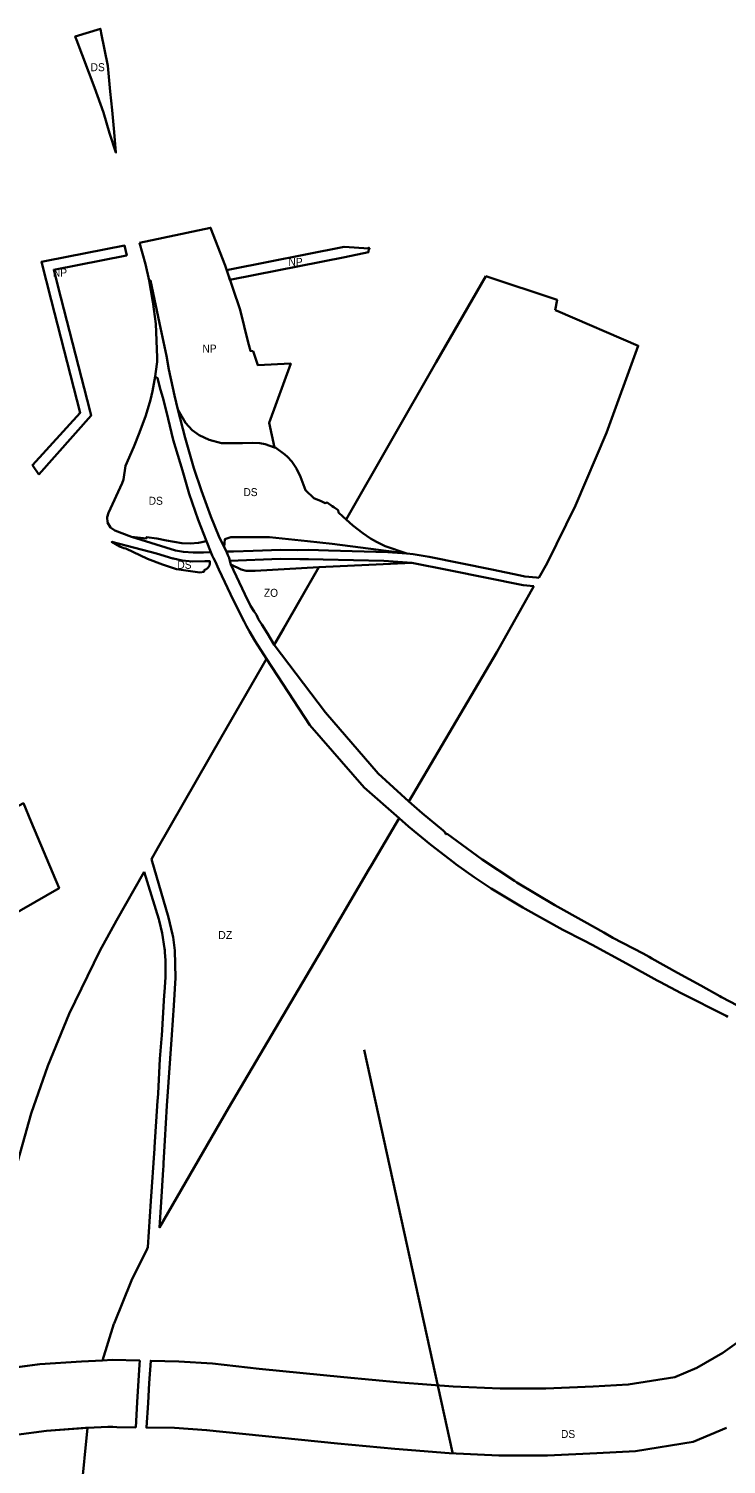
# Model space of a CAD drawing. Extents: x -650276 to -642489, y -1074311 to -1066658.
# Drawn here: x -647975 to -646929, y -1069108 to -1066956 of the extents above; entities that cross this region are included whole.
import ezdxf

# ---------------------------------------------------------------- set-up
doc = ezdxf.new("R2010")
doc.units = 0
doc.header["$LTSCALE"] = 4.8
doc.header["$PDMODE"] = 32
doc.header["$PDSIZE"] = 2.4
for name, color, linetype, lineweight in [('24', 7, 'Continuous', 35), ('25', 7, 'Continuous', 35), ('42', 7, 'Continuous', 35), ('48', 7, 'Continuous', 35), ('54', 7, 'Continuous', 35)]:
    doc.layers.add(name, color=color, linetype=linetype, lineweight=lineweight)
doc.layers.add('62', color=7, linetype='Continuous')
doc.layers.add('63', color=7, linetype='Continuous')

msp = doc.modelspace()

# ---------------------------------------------------------------- linework, layer by layer
at = {"layer": '24'}
for points in [[(-647876.57, -1067043.5), (-647863.04, -1067081.36), (-647853.65, -1067111.91), (-647844.3, -1067141.25), (-647847.09, -1067110.58), (-647850.07, -1067077.71), (-647852.63, -1067049.52), (-647856.11, -1067011.21), (-647866.14, -1066961.98), (-647867.46, -1066955.52), (-647905.28, -1066967.07), (-647903.5, -1066972.05)], [(-647754.88, -1067737.59), (-647743.12, -1067739.93), (-647728.29, -1067740.64), (-647713.15, -1067741), (-647702.21, -1067740.43), (-647708.71, -1067723.99), (-647720.45, -1067726.49), (-647732.71, -1067727.02), (-647745.41, -1067726.6), (-647768.53, -1067722.82), (-647783.13, -1067719.68), (-647798.17, -1067717.58), (-647798.5, -1067719.67), (-647821.02, -1067717.33)], [(-647596.91, -1067736.61), (-647572.33, -1067737.03), (-647555.58, -1067736.71), (-647525.685, -1067737.542), (-647436.72, -1067740.02), (-647408.2, -1067742.37), (-647520.145, -1067727.879), (-647557, -1067724), (-647614, -1067718), (-647643, -1067718), (-647672, -1067718), (-647680.804, -1067720.745), (-647681.91, -1067732.74), (-647678.66, -1067739.38), (-647678.66, -1067739.38), (-647667.76, -1067739.01), (-647638.75, -1067738.03)], [(-647540.208, -1067762.876), (-647400.63, -1067756.19), (-647442.6, -1067753.13), (-647533.597, -1067751.344), (-647555.67, -1067750.91), (-647568.36, -1067750.7), (-647597.83, -1067750.21), (-647673.47, -1067753.48), (-647672.05, -1067758.98), (-647672.05, -1067758.98), (-647656.469, -1067766.309), (-647649.22, -1067768.38), (-647635.758, -1067768.38)], [(-647540.208, -1067762.876), (-647400.63, -1067756.19), (-647442.6, -1067753.13), (-647533.597, -1067751.344), (-647555.67, -1067750.91), (-647568.36, -1067750.7), (-647597.83, -1067750.21), (-647673.47, -1067753.48), (-647672.05, -1067758.98), (-647672.05, -1067758.98), (-647656.469, -1067766.309), (-647649.22, -1067768.38), (-647635.758, -1067768.38)]]:
    msp.add_lwpolyline(points, close=True, dxfattribs=at)
for points in [[(-647606.818, -1067879.061), (-647617.25, -1067861.95), (-647625.37, -1067848.86), (-647630.3, -1067841.02), (-647633.69, -1067834.31), (-647637.21, -1067829.29), (-647642.29, -1067820.76), (-647650.8, -1067803.28), (-647672.05, -1067758.98), (-647673.47, -1067753.48), (-647673.47, -1067753.48), (-647674.67, -1067748.73), (-647676.47, -1067744.5), (-647678.66, -1067739.38), (-647681.91, -1067732.74), (-647690.09, -1067716.05), (-647702.04, -1067686.86), (-647715.92, -1067648.12), (-647727.37, -1067614.33), (-647740.49, -1067568.67), (-647751.41, -1067526.58), (-647756.55, -1067505.32), (-647759.16, -1067494.01), (-647764.89, -1067466.64), (-647768.5, -1067446.04), (-647778.78, -1067397.1), (-647792.52, -1067332.74), (-647794.54, -1067333.14), (-647788.77, -1067365.03), (-647784.55, -1067398.01), (-647782.39, -1067448.34), (-647782.5, -1067455.11), (-647784.36, -1067469.6), (-647785.64, -1067477.02), (-647781.85, -1067479.19), (-647777.55, -1067496.95), (-647773.96, -1067508.48), (-647768.5, -1067529.75), (-647758.25, -1067571.79), (-647744.61, -1067617.96), (-647734.63, -1067652.57), (-647721.05, -1067691.73), (-647708.71, -1067723.99), (-647702.21, -1067740.43), (-647699.89, -1067745.24), (-647697.85, -1067749.46), (-647695.71, -1067753.9), (-647690.19, -1067766.37), (-647668.13, -1067812.76), (-647651.94, -1067844.36), (-647648.33, -1067851.17), (-647643.83, -1067859.13), (-647635.77, -1067873.43), (-647618.773, -1067899.914)], [(-647708.71, -1067723.99), (-647721.05, -1067691.73), (-647734.63, -1067652.57), (-647744.61, -1067617.96), (-647758.25, -1067571.79), (-647768.5, -1067529.75), (-647773.96, -1067508.48), (-647777.55, -1067496.95), (-647781.85, -1067479.19), (-647785.64, -1067477.02), (-647789.39, -1067498.84), (-647792.54, -1067511.85), (-647799.39, -1067535.48)], [(-647799.39, -1067535.48), (-647808.71, -1067561.03), (-647817.59, -1067582.4)], [(-647654.743, -1067576.996), (-647685.968, -1067576.68), (-647704.458, -1067572.034), (-647719.661, -1067564.884), (-647729.802, -1067557.462), (-647740.124, -1067546.265), (-647751.41, -1067526.58)], [(-647751.41, -1067526.58), (-647740.49, -1067568.67), (-647727.37, -1067614.33), (-647715.92, -1067648.12), (-647702.04, -1067686.86)], [(-647817.59, -1067582.4), (-647829.97, -1067610.62), (-647832.8, -1067631.53), (-647835.06, -1067637.01), (-647855.24, -1067681.26), (-647857.51, -1067687.74), (-647856.9, -1067695.97)], [(-647606.559, -1067583.309), (-647620.586, -1067578.478), (-647628.441, -1067576.759), (-647640.087, -1067576.306), (-647654.743, -1067576.996)], [(-647547.663, -1067659.519), (-647560.187, -1067647.458), (-647567.744, -1067627.24), (-647573.605, -1067614.951), (-647580.539, -1067604.432), (-647586.864, -1067597.411), (-647591.227, -1067593.613), (-647604.415, -1067584.047), (-647606.559, -1067583.309)], [(-647499.095, -1067691.163), (-647503.97, -1067686.73), (-647510.6, -1067680.86), (-647511.24, -1067677.53), (-647517.74, -1067672.85), (-647520.13, -1067671.13), (-647527.76, -1067665.65), (-647530.82, -1067666.65), (-647536.83, -1067663.64), (-647547.663, -1067659.519)], [(-647702.04, -1067686.86), (-647690.09, -1067716.05), (-647681.91, -1067732.74)], [(-647462.45, -1067719.84), (-647474.13, -1067711.81), (-647489.3, -1067700.07), (-647499.095, -1067691.163)], [(-647856.9, -1067695.97), (-647852.3, -1067703.36), (-647845.74, -1067707.59), (-647821.02, -1067717.33)], [(-647783.54, -1067742.11), (-647850.45, -1067724.77), (-647838.18, -1067731.62), (-647832.56, -1067734.22), (-647829.49, -1067734.58), (-647796.87, -1067750.25), (-647774.54, -1067758.68), (-647753.53, -1067765.58), (-647718.54, -1067770.6), (-647712.01, -1067769.63), (-647712.26, -1067767.28)], [(-647821.02, -1067717.33), (-647798.5, -1067719.67), (-647798.17, -1067717.58), (-647783.13, -1067719.68), (-647768.53, -1067722.82), (-647745.41, -1067726.6), (-647732.71, -1067727.02), (-647720.45, -1067726.49), (-647708.71, -1067723.99)], [(-647681.91, -1067732.74), (-647680.804, -1067720.745), (-647672, -1067718), (-647643, -1067718), (-647614, -1067718)], [(-647614, -1067718), (-647557, -1067724), (-647520.145, -1067727.879), (-647408.2, -1067742.37), (-647440.81, -1067731.38), (-647453.87, -1067724.97), (-647462.45, -1067719.84)], [(-647712.26, -1067767.28), (-647711.773, -1067767.135), (-647711.286, -1067766.968), (-647710.799, -1067766.777), (-647710.315, -1067766.562), (-647709.834, -1067766.324), (-647709.359, -1067766.062), (-647708.892, -1067765.776), (-647708.433, -1067765.466), (-647707.985, -1067765.133), (-647707.55, -1067764.777), (-647707.128, -1067764.398), (-647706.723, -1067763.999), (-647706.335, -1067763.579), (-647705.966, -1067763.14), (-647705.617, -1067762.683), (-647705.29, -1067762.21), (-647704.985, -1067761.721), (-647704.704, -1067761.22), (-647704.447, -1067760.707), (-647704.216, -1067760.184), (-647704.01, -1067759.653), (-647703.83, -1067759.117), (-647703.675, -1067758.576), (-647703.547, -1067758.033), (-647703.445, -1067757.489), (-647703.368, -1067756.946), (-647703.315, -1067756.406), (-647703.287, -1067755.87), (-647703.282, -1067755.341), (-647703.3, -1067754.818), (-647703.34, -1067754.304), (-647703.4, -1067753.8), (-647711.09, -1067753.71), (-647728.98, -1067754.07), (-647734.69, -1067753.66), (-647744.74, -1067752.93), (-647757.74, -1067749.96), (-647759.13, -1067749.54), (-647783.54, -1067742.11)], [(-647405.026, -1068113.904), (-647451.024, -1068071.886), (-647530.038, -1067980.839), (-647606.818, -1067879.061)], [(-647618.773, -1067899.914), (-647553.628, -1067999.427), (-647472.338, -1068093.096), (-647419.713, -1068138.871)], [(-646864.48, -1068444.64), (-646936.47, -1068407.23), (-646938.95, -1068405.8), (-646967.64, -1068390), (-647002.71, -1068371.09), (-647040.77, -1068349.4), (-647044.93, -1068347.08), (-647053.75, -1068342.11), (-647099.2, -1068318.27), (-647112.813, -1068310.564), (-647142.41, -1068293.81), (-647186.26, -1068269.45), (-647243.39, -1068235.26), (-647246.8, -1068233.08), (-647295.47, -1068201.09), (-647347.74, -1068162.54), (-647349.59, -1068163.24), (-647350.6, -1068160.26), (-647353.81, -1068157.67), (-647385.13, -1068131.51), (-647405.026, -1068113.904)], [(-647419.713, -1068138.871), (-647405.71, -1068151.74), (-647372.38, -1068179.01), (-647337.74, -1068205.67), (-647334.62, -1068208.02), (-647307.39, -1068227.44), (-647281.64, -1068244.34), (-647234.11, -1068273.04), (-647230.83, -1068274.93), (-647174.56, -1068306.35), (-647142.788, -1068322.462), (-647130.29, -1068328.8), (-647079.16, -1068357.01), (-647032.91, -1068382.51), (-647029.23, -1068384.46), (-646997.06, -1068401.37), (-646929.56, -1068435.42), (-646927.06, -1068436.66)], [(-646894.206, -1068911.595), (-646934.465, -1068940.759), (-646973.61, -1068963.135), (-647006.63, -1068977.08), (-647076.422, -1068988.18), (-647128.674, -1068991.167), (-647199.672, -1068994.255), (-647268.348, -1068994.255), (-647338.816, -1068991.19), (-647417.895, -1068984.986), (-647502.412, -1068977.157), (-647629.424, -1068964.608), (-647699.561, -1068956.635), (-647749.978, -1068953.416), (-647792.01, -1068952.442), (-647794.21, -1068986.12), (-647796.13, -1069015.57), (-647798.631, -1069052.508), (-647756.441, -1069053.207), (-647708.401, -1069056.275), (-647511.94, -1069076.703), (-647426.417, -1069084.624), (-647344.902, -1069091.02), (-647270.522, -1069094.255), (-647197.498, -1069094.255), (-647123.648, -1069091.043), (-647065.688, -1069087.73), (-646978.92, -1069073.93), (-646929.186, -1069052.925)], [(-647864.531, -1068951.823), (-647895.901, -1068953.392), (-647958.168, -1068957.73), (-648038.596, -1068968.281), (-648038.759, -1068968.54)], [(-647808.28, -1068952.066), (-647850.043, -1068951.098), (-647864.531, -1068951.823)], [(-647814.401, -1069052.246), (-647812.34, -1069014.54), (-647808.67, -1068958.06), (-647808.28, -1068952.066)], [(-648040.705, -1069069.547), (-648039.666, -1069069.279), (-647948.18, -1069057.276), (-647886.615, -1069053.052), (-647856.541, -1069051.548), (-647848.615, -1069051.679), (-647842.888, -1069051.774), (-647814.401, -1069052.246)]]:
    msp.add_lwpolyline(points, dxfattribs=at)
at = {"layer": '25'}
msp.add_line((-648038.596, -1068968.281), (-647958.168, -1068957.73), dxfattribs=at)
for points in [[(-647289.924, -1067326.309), (-647364.024, -1067455.561), (-647499.095, -1067691.163), (-647489.3, -1067700.07)], [(-647185.93, -1067377.38), (-647183.09, -1067362.16), (-647289.924, -1067326.309)], [(-647210.537, -1067778.594), (-647198.088, -1067756.5), (-647155.592, -1067670.17), (-647108.971, -1067561.55), (-647061.252, -1067430.908), (-647181.878, -1067379.12), (-647185.93, -1067377.38)], [(-647489.3, -1067700.07), (-647474.13, -1067711.81), (-647462.45, -1067719.84), (-647453.87, -1067724.97), (-647440.81, -1067731.38), (-647408.2, -1067742.37), (-647398.74, -1067743.15)], [(-647398.74, -1067743.15), (-647374.55, -1067747.34), (-647280.78, -1067766.44), (-647237.91, -1067775.18), (-647231.17, -1067776.55), (-647213.92, -1067778.26), (-647210.537, -1067778.594)], [(-647400.63, -1067756.19), (-647540.208, -1067762.876), (-647593.267, -1067855.425), (-647606.818, -1067879.061)], [(-647217.611, -1067791.149), (-647233.83, -1067789.69), (-647345.11, -1067767.28), (-647400.63, -1067756.19)], [(-647405.026, -1068113.904), (-647273.297, -1067889.981), (-647217.611, -1067791.149)], [(-647606.818, -1067879.061), (-647530.038, -1067980.839), (-647451.024, -1068071.886), (-647405.026, -1068113.904)], [(-647464.94, -1068215.752), (-647461.188, -1068209.373), (-647419.713, -1068138.871), (-647472.338, -1068093.096), (-647553.628, -1067999.427), (-647618.773, -1067899.914), (-647685.819, -1068016.861)], [(-647685.819, -1068016.861), (-647781.346, -1068183.485), (-647791.055, -1068200.507)], [(-647791.055, -1068200.507), (-647765.22, -1068287.94), (-647759.412, -1068313.436)], [(-647801.797, -1068219.34), (-647843.6, -1068292.629), (-647868.214, -1068337.803), (-647914.339, -1068432.512), (-647946.187, -1068510.254), (-647971.074, -1068581.98), (-647997.27, -1068674.747), (-648011.775, -1068739.718), (-648023.914, -1068809.332), (-648030.73, -1068861.213), (-648038.596, -1068968.281)], [(-647771.413, -1068334.626), (-647774.94, -1068311.47), (-647779.55, -1068292.23), (-647780.07, -1068290.53), (-647801.797, -1068219.34)], [(-647768.02, -1068570.36), (-647770.94, -1068622.47), (-647772.85, -1068656.41), (-647773.08, -1068660.57), (-647773.4, -1068665.71), (-647776.5, -1068714.8), (-647778.95, -1068752.433), (-647675.054, -1068572.919), (-647535.844, -1068336.279), (-647464.94, -1068215.752)], [(-647759.412, -1068313.436), (-647758.45, -1068317.66), (-647756.09, -1068337.61), (-647754.99, -1068378.21), (-647757.41, -1068419.98), (-647760.22, -1068463.96), (-647768.02, -1068570.36)], [(-647796.173, -1068782.191), (-647791.77, -1068713.23), (-647786.47, -1068634.37), (-647786.32, -1068632.19), (-647781.85, -1068562.97), (-647781.55, -1068558.38), (-647781.13, -1068551.88), (-647778.24, -1068499.95), (-647775.82, -1068469.74), (-647775.52, -1068464.97), (-647771.74, -1068404.5), (-647771.47, -1068400.07), (-647770.12, -1068377.5), (-647769.92, -1068352.1), (-647770.81, -1068340.29), (-647771.05, -1068337.01), (-647771.413, -1068334.626)], [(-647846.989, -1068896.545), (-647820.883, -1068832.117), (-647797.632, -1068784.713), (-647796.173, -1068782.191)], [(-647958.168, -1068957.73), (-647895.901, -1068953.392), (-647864.531, -1068951.823), (-647847.197, -1068897.199), (-647847.034, -1068896.687), (-647846.989, -1068896.545)], [(-647948.18, -1069057.276), (-648039.666, -1069069.279), (-648040.705, -1069069.548), (-648036.291, -1069139.458)], [(-647886.615, -1069053.052), (-647889.927, -1069053.218), (-647948.18, -1069057.276)], [(-647893.553, -1069279.017), (-647896.67, -1069213.573), (-647896.362, -1069149.171), (-647886.615, -1069053.052)]]:
    msp.add_lwpolyline(points, dxfattribs=at)
at = {"layer": '42'}
msp.add_lwpolyline([(-647606.818, -1067879.061), (-647540.208, -1067762.876), (-647635.758, -1067768.38), (-647649.22, -1067768.38), (-647656.469, -1067766.309), (-647672.05, -1067758.98), (-647650.8, -1067803.28), (-647642.29, -1067820.76), (-647637.21, -1067829.29), (-647633.69, -1067834.31), (-647630.3, -1067841.02), (-647625.37, -1067848.86), (-647617.25, -1067861.95)], close=True, dxfattribs=at)
at = {"layer": '48'}
for points in [[(-647638.68, -1067439.06), (-647642.686, -1067438.46), (-647645.78, -1067425.81), (-647658.13, -1067376.99), (-647680.64, -1067310.37), (-647702.42, -1067253.98), (-647809.02, -1067276.271)], [(-647882.66, -1067529.231), (-647926.759, -1067358.379), (-647937.355, -1067316.774), (-647828.376, -1067295.406), (-647828.104, -1067295.352), (-647831.28, -1067280.69), (-647948.488, -1067303.671)], [(-647809.02, -1067276.271), (-647799.76, -1067308.3), (-647794.54, -1067333.14)], [(-647948.488, -1067303.671), (-647955.805, -1067305.106), (-647941.289, -1067362.104)], [(-647465.203, -1067285.115), (-647501.968, -1067282.642), (-647673.685, -1067316.666), (-647678.21, -1067317.562), (-647673.367, -1067331.895), (-647670.77, -1067331.38), (-647501.099, -1067297.762)], [(-647501.099, -1067297.762), (-647465.699, -1067290.747), (-647465.203, -1067285.115)], [(-647794.54, -1067333.14), (-647792.52, -1067332.74), (-647778.78, -1067397.1), (-647768.5, -1067446.04), (-647764.89, -1067466.64), (-647759.16, -1067494.01)], [(-647941.289, -1067362.104), (-647897.637, -1067531.223), (-647969.29, -1067609.79), (-647959.832, -1067623.65)], [(-647751.41, -1067526.58), (-647740.124, -1067546.265), (-647729.802, -1067557.462), (-647719.661, -1067564.884), (-647704.458, -1067572.034), (-647685.968, -1067576.68), (-647654.743, -1067576.996), (-647640.087, -1067576.306), (-647628.441, -1067576.759), (-647620.586, -1067578.478), (-647606.559, -1067583.309), (-647614.75, -1067546.53), (-647582.2, -1067457.65), (-647631.59, -1067459.72), (-647638.68, -1067439.06)], [(-647759.16, -1067494.01), (-647756.55, -1067505.32), (-647751.41, -1067526.58)], [(-647959.832, -1067623.65), (-647881.085, -1067535.333), (-647882.66, -1067529.231)]]:
    msp.add_lwpolyline(points, dxfattribs=at)
msp.add_lwpolyline([(-648101.42, -1068344.28), (-648079.33, -1068330.03), (-647929.45, -1068244.16), (-647971.35, -1068144.48), (-647982.969, -1068116.575), (-648165.28, -1068214.465)], close=True, dxfattribs=at)
msp.add_point((-647465.203, -1067285.115), dxfattribs=at)
at = {"layer": '54'}
msp.add_line((-647472.11, -1068486.2), (-647340, -1069090), dxfattribs=at)

# ---------------------------------------------------------------- texts
at = {"layer": '62', "width": 0.95}
for s, p in [('NP', (-647585.583, -1067311.041)), ('NP', (-647938.583, -1067327.041)), ('NP', (-647714.583, -1067441.041)), ('DS', (-647653.118, -1067656.225)), ('DS', (-647795.118, -1067669.225)), ('DS', (-647752.118, -1067765.225)), ('ZO', (-647622.423, -1067807.188)), ('DS', (-647177.118, -1069068.225))]:
    msp.add_text(s, height=12, dxfattribs=at).set_placement(p)
at = {"layer": '62'}
msp.add_text('DZ', height=12, dxfattribs=at).set_placement((-647691.118, -1068320.225))
at = {"layer": '63', "width": 0.95}
msp.add_text('DS', height=12, dxfattribs=at).set_placement((-647882.118, -1067019.225))

doc.saveas('drawing.dxf')
